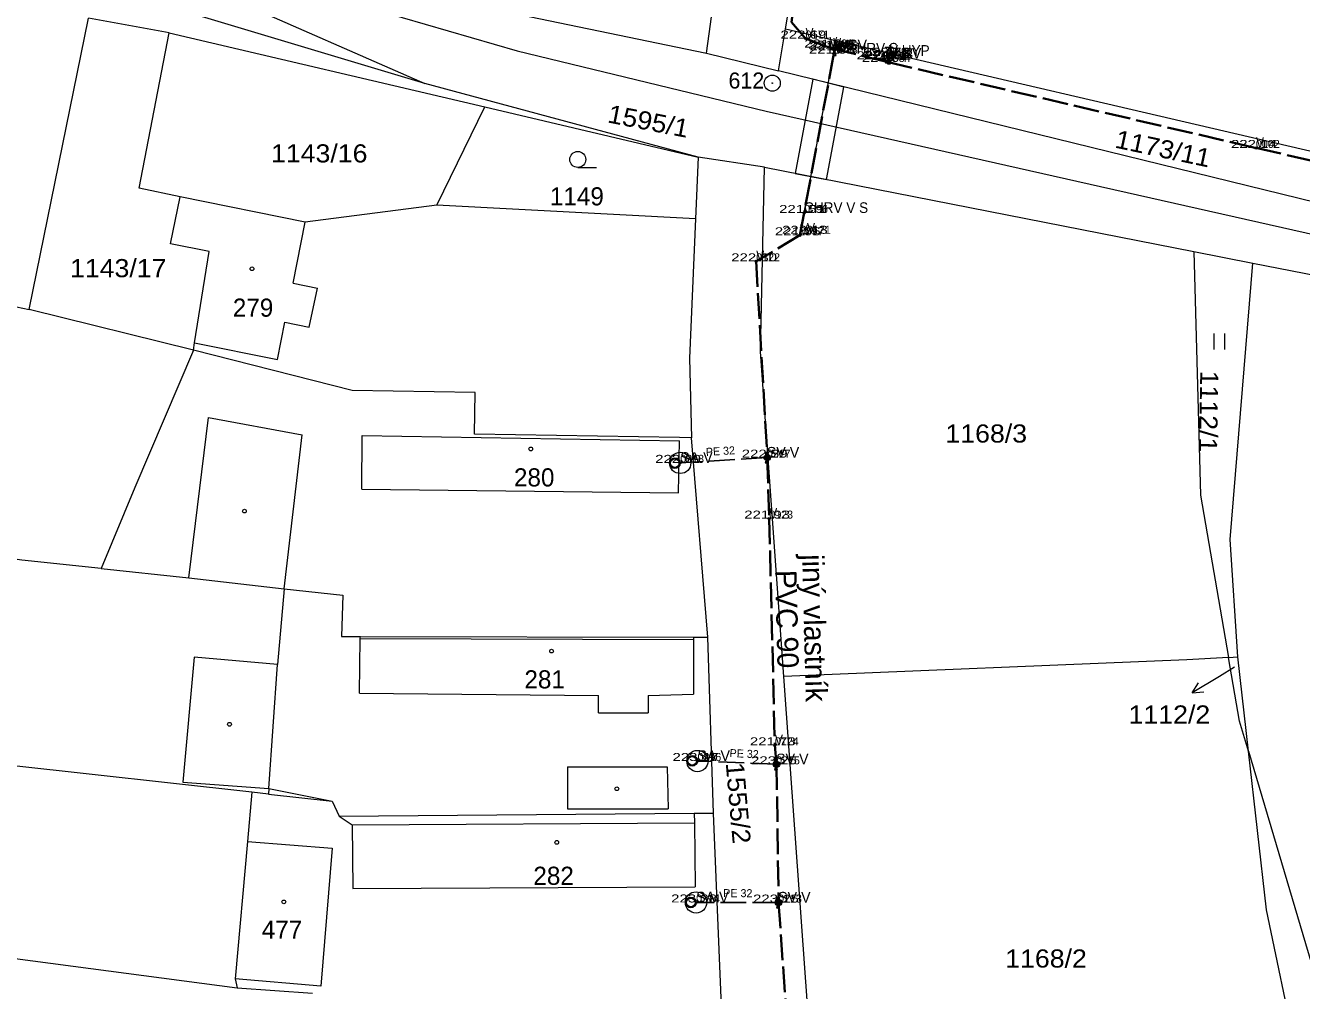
# Model space of a CAD drawing. Extents: x -686207 to -681951, y -1020493 to -1017811.
# Drawn here: x -684334 to -684214.5, y -1019268.5 to -1019178.1 of the extents above; entities that cross this region are included whole.
import ezdxf
from ezdxf.enums import TextEntityAlignment as Align

# ---------------------------------------------------------------- set-up
doc = ezdxf.new("R2010")
doc.units = 0
doc.header["$LTSCALE"] = 0.4
doc.header["$PDMODE"] = 32
doc.header["$PDSIZE"] = 0.2
doc.linetypes.add('DOTTED', pattern=[1.5, 0.3, -1.2])
doc.linetypes.add('LONG_DASHED', pattern=[7.5, 6, -1.5])
for name, color, linetype, lineweight in [('1', 7, 'Continuous', 13), ('10', 7, 'Continuous', 13), ('12', 7, 'Continuous', 13), ('13', 7, 'Continuous', 13), ('25', 7, 'Continuous', 13), ('3', 7, 'Continuous', 13), ('35', 7, 'LONG_DASHED', 35), ('4', 7, 'Continuous', 13), ('5', 7, 'Continuous', 13), ('50', 7, 'LONG_DASHED', 25), ('51', 7, 'DOTTED', 25), ('6', 7, 'Continuous', 13), ('7', 7, 'Continuous', 13), ('8', 7, 'Continuous', 13)]:
    doc.layers.add(name, color=color, linetype=linetype, lineweight=lineweight)
for name, color, linetype in [('17', 7, 'Continuous'), ('19', 7, 'Continuous'), ('2', 7, 'Continuous')]:
    doc.layers.add(name, color=color, linetype=linetype)

msp = doc.modelspace()

# ---------------------------------------------------------------- linework, layer by layer
at = {"layer": '1'}
for p, q in [((-684270.21, -1019180.68), (-684268.07, -1019165.17)), ((-684322.71, -1019172.07), (-684296.61, -1019183.52)), ((-684333.66, -1019204.71), (-684328.11, -1019177.42)), ((-684296.61, -1019183.52), (-684317.84, -1019177.17)), ((-684320.56, -1019178.77), (-684290.97, -1019185.73)), ((-684263.48, -1019182.35), (-684262.82, -1019178.4)), ((-684262.82, -1019178.4), (-684209.29, -1019190.88)), ((-684270.21, -1019180.68), (-684263.48, -1019182.35)), ((-684295.49, -1019194.94), (-684290.97, -1019185.73)), ((-684264.79, -1019191.38), (-684271.01, -1019190.42)), ((-684264.79, -1019191.38), (-684224.56, -1019199.27)), ((-684391.53, -1019192.59), (-684333.66, -1019204.71)), ((-684307.83, -1019196.53), (-684319.52, -1019194.14)), ((-684295.49, -1019194.94), (-684307.83, -1019196.53)), ((-684224.56, -1019199.27), (-684219.03, -1019200.36)), ((-684219.03, -1019200.36), (-684209.35, -1019202.26)), ((-684318.28, -1019208.52), (-684333.66, -1019204.71)), ((-684303.4, -1019212.3), (-684318.28, -1019208.52)), ((-684221.3, -1019237.3), (-684220.44, -1019237.25)), ((-684219.43, -1019246.09), (-684220.44, -1019237.25)), ((-684259.33, -1019289.49), (-684262.97, -1019239.09)), ((-684219.43, -1019246.09), (-684207.19, -1019287.34)), ((-684312.81, -1019249.93), (-684313.22, -1019254.55)), ((-684311.26, -1019250.1), (-684312.81, -1019249.93)), ((-684268.79, -1019270.7), (-684269.57, -1019251.88)), ((-684313.22, -1019254.55), (-684314.38, -1019267.41)), ((-684385.64, -1019258.86), (-684314.18, -1019268.24)), ((-684314.18, -1019268.24), (-684307.13, -1019268.75))]:
    msp.add_line(p, q, dxfattribs=at)
for points in [[(-684262.82, -1019178.4), (-684260.07, -1019162.03), (-684255.51, -1019132.38), (-684246.85, -1019134.12)], [(-684303.6, -1019171.9), (-684292.25, -1019176.13), (-684270.21, -1019180.68)], [(-684319.52, -1019194.14), (-684323.36, -1019193.35), (-684320.56, -1019178.77), (-684328.11, -1019177.42)], [(-684203.15, -1019196.83), (-684208.13, -1019195.68), (-684208.2, -1019195.9), (-684263.48, -1019182.35)], [(-684290.97, -1019185.73), (-684271.01, -1019190.42), (-684296.61, -1019183.52)], [(-684271.01, -1019190.42), (-684271.26, -1019196.22), (-684295.49, -1019194.94)], [(-684262.97, -1019239.09), (-684265.17, -1019208.68), (-684264.79, -1019191.38)], [(-684318.28, -1019208.52), (-684318.17, -1019207.84), (-684316.8, -1019199.28), (-684320.42, -1019198.54), (-684319.52, -1019194.14)], [(-684271.26, -1019196.22), (-684271.82, -1019209.26), (-684271.61, -1019216.72)], [(-684224.56, -1019199.27), (-684223.94, -1019222.08), (-684221.3, -1019237.3)], [(-684220.44, -1019237.25), (-684221.16, -1019226.24), (-684219.03, -1019200.36)], [(-684318.28, -1019208.52), (-684323.78, -1019221.38), (-684326.93, -1019228.97)], [(-684271.61, -1019216.72), (-684272.74, -1019216.7), (-684291.96, -1019216.38), (-684291.9, -1019212.48), (-684303.4, -1019212.3)], [(-684269.57, -1019251.88), (-684270.09, -1019235.4), (-684271.61, -1019216.72)], [(-684326.93, -1019228.97), (-684334.37, -1019228.17), (-684395.77, -1019219.45)], [(-684326.93, -1019228.97), (-684318.7, -1019229.85), (-684309.77, -1019230.88)], [(-684309.77, -1019230.88), (-684310.4, -1019237.97), (-684318.23, -1019237.27), (-684319.27, -1019248.99), (-684311.22, -1019249.56), (-684311.26, -1019250.1)], [(-684309.77, -1019230.88), (-684304.3, -1019231.47), (-684304.4, -1019235.32), (-684302.64, -1019235.33), (-684271.44, -1019235.4), (-684270.09, -1019235.4)], [(-684221.3, -1019237.3), (-684225.21, -1019237.53), (-684262.97, -1019239.09)], [(-684219.43, -1019246.09), (-684220.27, -1019243.27), (-684221.3, -1019237.3)], [(-684312.81, -1019249.93), (-684335.38, -1019247.43), (-684400.12, -1019240.26)], [(-684212.19, -1019287.54), (-684217.74, -1019260.95), (-684219.43, -1019246.09)], [(-684311.26, -1019250.1), (-684305.3, -1019250.76), (-684304.63, -1019252.17), (-684271.36, -1019251.9), (-684269.57, -1019251.88)], [(-684313.22, -1019254.55), (-684305.27, -1019255.17), (-684306.36, -1019268.09), (-684314.38, -1019267.41), (-684314.18, -1019268.24)]]:
    msp.add_lwpolyline(points, dxfattribs=at)
for p in [(-684260.94, -1019179.32), (-684258.71, -1019180.16), (-684258.35, -1019180.28), (-684258.22, -1019180.42), (-684258.28, -1019180.73), (-684253.82, -1019181.27), (-684253.32, -1019181.51), (-684253.12, -1019180.94), (-684253.12, -1019181.2), (-684218.74, -1019189.57), (-684261.07, -1019195.66), (-684261.47, -1019197.75), (-684260.8, -1019197.61), (-684265.56, -1019200.19), (-684264.57, -1019218.58), (-684272.68, -1019219.07), (-684264.34, -1019224.29), (-684263.81, -1019245.53), (-684271.06, -1019247), (-684263.7, -1019247.31), (-684271.19, -1019260.25), (-684263.51, -1019260.26)]:
    msp.add_point(p, dxfattribs=at)
at = {"layer": '10'}
for p, q in [((-684253.47, -1019180.14), (-684252.77, -1019180.14)), ((-684253.12, -1019180.44), (-684253.12, -1019180.14)), ((-684253.474, -1019181.294), (-684252.767, -1019180.587))]:
    msp.add_line(p, q, dxfattribs=at)
for points in [[(-684258.07, -1019180.92), (-684258.37, -1019179.92), (-684258.07, -1019179.92), (-684258.37, -1019180.92)], [(-684252.97, -1019181.7), (-684253.27, -1019180.7), (-684252.97, -1019180.7), (-684253.27, -1019181.7)], [(-684264.42, -1019219.08), (-684264.72, -1019218.08), (-684264.42, -1019218.08), (-684264.72, -1019219.08)], [(-684263.55, -1019247.81), (-684263.85, -1019246.81), (-684263.55, -1019246.81), (-684263.85, -1019247.81)], [(-684263.36, -1019260.76), (-684263.66, -1019259.76), (-684263.36, -1019259.76), (-684263.66, -1019260.76)]]:
    msp.add_lwpolyline(points, close=True, dxfattribs=at)
for centre, radius in [((-684253.119, -1019180.94), 0.5), ((-684272.68, -1019219.07), 1), ((-684271.06, -1019247), 1), ((-684271.19, -1019260.25), 1)]:
    msp.add_circle(centre, radius, dxfattribs=at)
at = {"layer": '12'}
for centre, radius in [((-684258.35, -1019180.28), 0.15), ((-684258.35, -1019180.28), 0.075), ((-684253.32, -1019181.51), 0.15), ((-684253.32, -1019181.51), 0.075), ((-684273.179, -1019219.1), 0.5), ((-684264.52, -1019218.577), 0.3), ((-684264.52, -1019218.577), 0.2), ((-684264.52, -1019218.577), 0.1), ((-684273.179, -1019219.1), 0.4), ((-684271.56, -1019246.979), 0.5), ((-684271.56, -1019246.979), 0.4), ((-684263.65, -1019247.312), 0.3), ((-684263.65, -1019247.312), 0.2), ((-684263.65, -1019247.312), 0.1), ((-684271.69, -1019260.249), 0.5), ((-684271.69, -1019260.249), 0.4), ((-684263.46, -1019260.26), 0.3), ((-684263.46, -1019260.26), 0.2), ((-684263.46, -1019260.26), 0.1)]:
    msp.add_circle(centre, radius, dxfattribs=at)
at = {"layer": '13'}
msp.add_lwpolyline([(-684260.26, -1019183.14), (-684261.91, -1019191.95), (-684258.97, -1019192.52), (-684257.34, -1019183.86)], close=True, dxfattribs=at)
at = {"layer": '25'}
msp.add_line((-684261.07, -1019195.66), (-684258.28, -1019180.73), dxfattribs=at)
at = {"layer": '3'}
for p, q in [((-684282.273, -1019191.4), (-684280.523, -1019191.4)), ((-684222.641, -1019208.46), (-684222.641, -1019206.96)), ((-684221.64, -1019208.46), (-684221.64, -1019206.96))]:
    msp.add_line(p, q, dxfattribs=at)
msp.add_circle((-684282.2729, -1019190.6498), 0.75, dxfattribs=at)
at = {"layer": '35'}
for p, q in [((-684258.35, -1019180.28), (-684258.22, -1019180.42)), ((-684253.32, -1019181.51), (-684258.35, -1019180.28)), ((-684253.12, -1019181.2), (-684253.32, -1019181.51)), ((-684253.12, -1019181.2), (-684253.12, -1019180.94))]:
    msp.add_line(p, q, dxfattribs=at)
for points in [[(-684258.35, -1019180.28), (-684258.71, -1019180.16), (-684260.94, -1019179.32), (-684262.26, -1019177.78), (-684260.891, -1019167.669)], [(-684258.22, -1019180.42), (-684258.28, -1019180.73), (-684261.07, -1019195.66), (-684261.47, -1019197.75), (-684265.56, -1019200.19), (-684264.52, -1019218.577)], [(-684253.32, -1019181.51), (-684218.74, -1019189.57), (-684187.75, -1019196.6), (-684161.31, -1019202.33), (-684135.19, -1019208.18), (-684108.74, -1019214.75), (-684082.37, -1019222.33), (-684055.68, -1019231.47), (-684028.78, -1019241.13), (-684001.7, -1019252), (-683976.78, -1019261.52), (-683963.28, -1019265.94), (-683954.22, -1019264.32), (-683949.59, -1019261.5)], [(-684264.52, -1019218.577), (-684264.34, -1019224.29), (-684263.81, -1019245.53), (-684263.65, -1019247.312), (-684263.46, -1019260.26)], [(-684263.46, -1019260.26), (-684262.51, -1019273.71), (-684262.141, -1019277.11)]]:
    msp.add_lwpolyline(points, dxfattribs=at)
at = {"layer": '4'}
for p, q in [((-684308.93, -1019202.22), (-684307.83, -1019196.53)), ((-684308.93, -1019202.22), (-684306.65, -1019202.71)), ((-684307.44, -1019206.37), (-684306.65, -1019202.71)), ((-684318.17, -1019207.84), (-684310.4, -1019209.39)), ((-684309.77, -1019230.88), (-684308.1, -1019216.43)), ((-684272.84, -1019221.88), (-684272.75, -1019217)), ((-684302.5, -1019221.52), (-684272.84, -1019221.88)), ((-684302.65, -1019235.51), (-684302.64, -1019235.33)), ((-684271.44, -1019235.4), (-684271.44, -1019235.62)), ((-684311.22, -1019249.56), (-684310.4, -1019237.97)), ((-684302.74, -1019240.63), (-684280.33, -1019240.85)), ((-684280.33, -1019242.5), (-684280.33, -1019240.85)), ((-684275.68, -1019240.85), (-684271.43, -1019240.75)), ((-684275.68, -1019240.85), (-684275.68, -1019242.5)), ((-684280.33, -1019242.5), (-684275.68, -1019242.5)), ((-684283.25, -1019247.56), (-684273.89, -1019247.56)), ((-684283.25, -1019247.56), (-684283.24, -1019251.47)), ((-684273.89, -1019247.56), (-684273.8, -1019251.47)), ((-684311.22, -1019249.56), (-684305.3, -1019250.76)), ((-684283.24, -1019251.47), (-684273.8, -1019251.47)), ((-684271.36, -1019251.9), (-684271.35, -1019252.8)), ((-684304.63, -1019252.17), (-684303.42, -1019252.97)), ((-684303.42, -1019252.97), (-684271.35, -1019252.8)), ((-684303.42, -1019252.97), (-684303.36, -1019258.93)), ((-684271.35, -1019252.8), (-684271.27, -1019258.78)), ((-684303.36, -1019258.93), (-684271.27, -1019258.78))]:
    msp.add_line(p, q, dxfattribs=at)
for points in [[(-684310.4, -1019209.39), (-684309.72, -1019205.88), (-684307.44, -1019206.37)], [(-684318.7, -1019229.85), (-684316.86, -1019214.83), (-684308.1, -1019216.43)], [(-684302.5, -1019221.52), (-684302.48, -1019216.51), (-684272.75, -1019217)], [(-684302.74, -1019240.63), (-684302.65, -1019235.51), (-684271.44, -1019235.62), (-684271.43, -1019240.75)]]:
    msp.add_lwpolyline(points, dxfattribs=at)
at = {"layer": '5'}
for centre in [(-684312.7968, -1019200.8892), (-684286.6768, -1019217.7692), (-684313.5068, -1019223.5892), (-684284.7268, -1019236.6992), (-684314.9068, -1019243.5592), (-684278.6168, -1019249.5992), (-684284.2468, -1019254.6192), (-684309.8168, -1019260.1992)]:
    msp.add_circle(centre, 0.175, dxfattribs=at)
at = {"layer": '50'}
for p, q in [((-684264.57, -1019218.58), (-684272.68, -1019219.07)), ((-684264.52, -1019218.577), (-684264.57, -1019218.58)), ((-684263.51, -1019260.26), (-684271.19, -1019260.25)), ((-684263.51, -1019260.26), (-684263.46, -1019260.26))]:
    msp.add_line(p, q, dxfattribs=at)
msp.add_lwpolyline([(-684263.65, -1019247.312), (-684263.7, -1019247.31), (-684271.06, -1019247)], dxfattribs=at)
at = {"layer": '51'}
for p, q in [((-684272.68, -1019219.07), (-684273.179, -1019219.1)), ((-684271.06, -1019247), (-684271.56, -1019246.979)), ((-684271.19, -1019260.25), (-684271.69, -1019260.249))]:
    msp.add_line(p, q, dxfattribs=at)
at = {"layer": '6'}
for p, q in [((-684305.27, -1019175.44), (-684287.96, -1019180.46)), ((-684287.96, -1019180.46), (-684264.61, -1019186.11)), ((-684264.61, -1019186.11), (-684208.8, -1019198.69))]:
    msp.add_line(p, q, dxfattribs=at)
at = {"layer": '7'}
msp.add_line((-684224.722, -1019240.616), (-684223.606, -1019240.529), dxfattribs=at)
msp.add_lwpolyline([(-684220.76, -1019238.22), (-684222.15, -1019239.07), (-684224.722, -1019240.616), (-684224.122, -1019239.671)], dxfattribs=at)
at = {"layer": '8'}
for radius in [0.75, 0.03]:
    msp.add_circle((-684264.05, -1019183.4998), radius, dxfattribs=at)

# ---------------------------------------------------------------- texts
at = {"layer": '17'}
for s, p in [('jiný vlastník', (-684261.0828, -1019234.5631)), ('PVC 90', (-684263.6747, -1019233.7316))]:
    msp.add_text(s, height=2, rotation=271.429, dxfattribs=at).set_placement(p, align=Align.CENTER)
at = {"layer": '19'}
for rotation, p in [(3.458, (-684268.8911, -1019218.3402)), (357.588, (-684266.7018, -1019246.6832)), (359.925, (-684267.28, -1019259.7548))]:
    msp.add_text('PE 32', height=0.75, rotation=rotation, dxfattribs=at).set_placement(p, align=Align.CENTER)
at = {"layer": '2'}
for s, height, p in [('0171', 0.75, (-684260.94, -1019179.32)), ('0086', 0.75, (-684258.71, -1019180.16)), ('0085', 0.75, (-684258.35, -1019180.28)), ('0088', 0.75, (-684258.28, -1019180.73)), ('0087', 0.75, (-684258.22, -1019180.42)), ('0082', 0.75, (-684253.12, -1019180.94)), ('0001', 0.75, (-684253.82, -1019181.27)), ('0084', 0.75, (-684253.32, -1019181.51)), ('0083', 0.75, (-684253.12, -1019181.2)), ('0002', 0.75, (-684218.74, -1019189.57)), ('1149', 1.7, (-684284.887, -1019194.95)), ('0096', 0.75, (-684261.07, -1019195.66)), ('0097', 0.75, (-684261.47, -1019197.75)), ('0121', 0.75, (-684260.8, -1019197.61)), ('0122', 0.75, (-684265.56, -1019200.19)), ('279', 1.7, (-684314.594, -1019205.38)), ('0218', 0.75, (-684272.68, -1019219.07)), ('0217', 0.75, (-684264.57, -1019218.58)), ('280', 1.7, (-684288.254, -1019221.28)), ('0123', 0.75, (-684264.34, -1019224.29)), ('281', 1.7, (-684287.274, -1019240.2)), ('0124', 0.75, (-684263.81, -1019245.53)), ('0216', 0.75, (-684271.06, -1019247)), ('0215', 0.75, (-684263.7, -1019247.31)), ('282', 1.7, (-684286.434, -1019258.6)), ('0214', 0.75, (-684271.19, -1019260.25)), ('0213', 0.75, (-684263.51, -1019260.26)), ('477', 1.7, (-684311.884, -1019263.65))]:
    msp.add_text(s, height=height, dxfattribs=at).set_placement(p)
at = {"layer": '2', "width": 1.1}
for s, rotation, p in [('1595/1', 349, (-684279.572, -1019187.164)), ('1173/11', 348, (-684232.036, -1019189.521)), ('1112/1', 269, (-684223.949, -1019210.415)), ('1555/2', 275, (-684268.414, -1019247.2))]:
    msp.add_text(s, height=1.7, rotation=rotation, dxfattribs=at).set_placement(p)
for s, p in [('1143/16', (-684311.018, -1019190.929)), ('1143/17', (-684329.85, -1019201.679)), ('1168/3', (-684247.83, -1019217.169)), ('1112/2', (-684230.67, -1019243.49)), ('1168/2', (-684242.23, -1019266.35))]:
    msp.add_text(s, height=1.7, dxfattribs=at).set_placement(p)
at = {"layer": '3', "width": 1.4}
for s, p in [('222 69 ', (-684260.94, -1019179.32)), ('221 64 ', (-684258.71, -1019180.16)), ('221 48 ', (-684258.35, -1019180.28)), ('221 38 ', (-684258.28, -1019180.73)), ('221 62 ', (-684258.22, -1019180.42)), ('223 72 ', (-684253.12, -1019180.94)), ('222 46 ', (-684253.82, -1019181.27)), ('224 04 ', (-684253.32, -1019181.51)), ('224 06 ', (-684253.12, -1019181.2)), ('222 14 ', (-684218.74, -1019189.57)), ('221 51 ', (-684261.07, -1019195.66)), ('221 76 ', (-684261.47, -1019197.75)), ('222 13 ', (-684260.8, -1019197.61)), ('222 30 ', (-684265.56, -1019200.19)), ('222 69 ', (-684272.68, -1019219.07)), ('222 59 ', (-684264.57, -1019218.58)), ('221 93 ', (-684264.34, -1019224.29)), ('221 73 ', (-684263.81, -1019245.53)), ('223 47 ', (-684271.06, -1019247)), ('223 25 ', (-684263.7, -1019247.31)), ('223 38 ', (-684271.19, -1019260.25)), ('223 15 ', (-684263.51, -1019260.26))]:
    msp.add_text(s, height=0.75, dxfattribs=at).set_placement(p, align=Align.CENTER)
at = {"layer": '4'}
for s, width, p in [('V', 0.85, (-684260.94, -1019179.32)), ('V', 0.85, (-684258.71, -1019180.16)), ('V', 0.85, (-684258.35, -1019180.28)), ('V CHRV S', 0.95, (-684258.28, -1019180.73)), ('V', 0.85, (-684253.82, -1019181.27)), ('V HYP', 0.95, (-684253.12, -1019180.94)), ('V', 0.85, (-684253.32, -1019181.51)), ('V', 0.85, (-684218.74, -1019189.57)), ('CHRV V S', 0.95, (-684261.07, -1019195.66)), ('V', 0.85, (-684261.47, -1019197.75)), ('V', 0.85, (-684260.8, -1019197.61)), ('V', 0.85, (-684265.56, -1019200.19)), ('V', 0.85, (-684264.34, -1019224.29)), ('V', 0.85, (-684263.81, -1019245.53))]:
    msp.add_text(s, height=1, dxfattribs=dict(at, width=width)).set_placement(p)
for s, p in [('V SV', (-684258.22, -1019180.42)), ('V SV', (-684253.12, -1019181.2)), ('SA V', (-684272.68, -1019219.07)), ('SV V', (-684264.57, -1019218.58)), ('SA V', (-684271.06, -1019247)), ('SV V', (-684263.7, -1019247.31)), ('SA V', (-684271.19, -1019260.25)), ('SV V', (-684263.51, -1019260.26))]:
    msp.add_text(s, height=1, dxfattribs=at).set_placement(p)
at = {"layer": '8'}
msp.add_text('612', height=1.5, dxfattribs=at).set_placement((-684268.153, -1019184))

doc.saveas('drawing.dxf')
